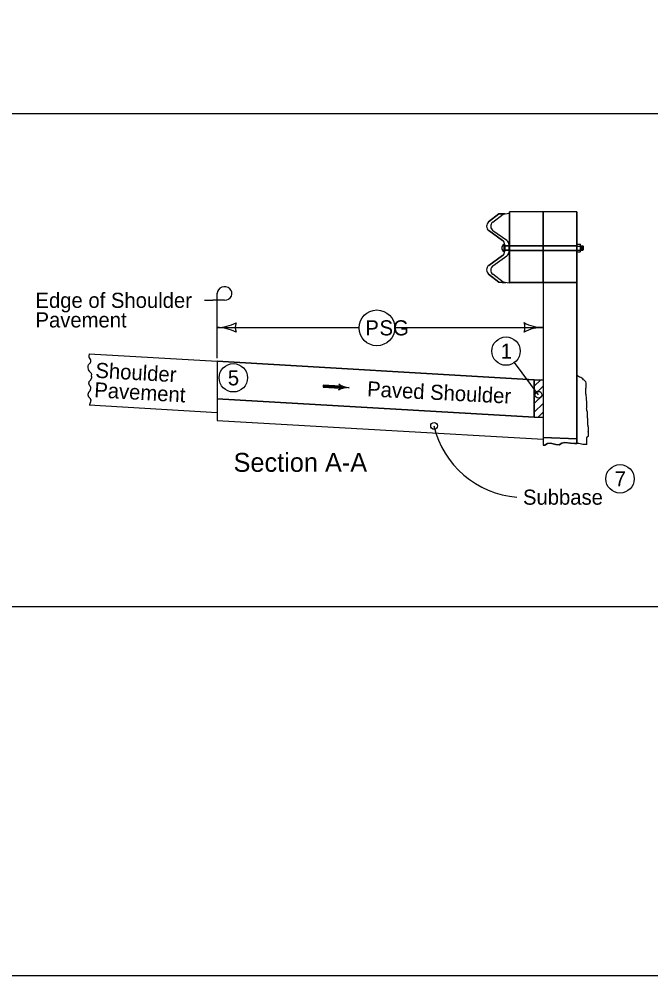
# Model space of a CAD drawing. Extents: x 8045 to 81668, y 6217 to 16762.
# Drawn here: x 10335 to 11002, y 7924 to 8935 of the extents above; entities that cross this region are included whole.
import ezdxf

# ---------------------------------------------------------------- set-up
doc = ezdxf.new("R2010")
doc.units = 0
for name, color, linetype in [('dsnStdDetailExtension', 7, 'Continuous'), ('dsnStdDimension', 7, 'Continuous'), ('dsnStdLabel', 7, 'Continuous'), ('dsnStdLineWork', 7, 'Continuous'), ('dsnStdPattern', 7, 'Continuous'), ('dsnStdSection', 7, 'Continuous'), ('Level 4', 7, 'Continuous'), ('Level 8', 7, 'Continuous'), ('TextBlockOut', 7, 'Continuous')]:
    doc.layers.add(name, color=color, linetype=linetype)

msp = doc.modelspace()

# ---------------------------------------------------------------- linework, layer by layer
at = {"layer": 'dsnStdDetailExtension'}
msp.add_circle((10773.3, 8505.4), 3.54, dxfattribs=at)
msp.add_circle((10773.3, 8505.4), 3.54, dxfattribs=at)
at = {"layer": 'dsnStdDimension'}
msp.add_line((10152.2, 8314.4), (13247.9, 8314.4), dxfattribs=at)
at = {"layer": 'dsnStdLabel'}
for p, q in [((10831, 8721.1), (10841.8, 8729.5)), ((10835.4, 8720.8), (10846.2, 8729.3)), ((10841.8, 8729.5), (10848.1, 8729.6)), ((10846.2, 8729.3), (10852.6, 8730.4)), ((10924.1, 8731.8), (10853, 8731.8)), ((10853, 8657.2), (10853, 8731.8)), ((10888.5, 8657.2), (10888.5, 8731.8)), ((10924.1, 8731.8), (10924.1, 8486.8)), ((10845.7, 8701.5), (10831.2, 8712)), ((10850.2, 8701.3), (10835.6, 8711.8)), ((10924.1, 8700.1), (10924.7, 8700.1)), ((10924.7, 8686.8), (10924.7, 8700.1)), ((10847.3, 8689.4), (10847.3, 8697.5)), ((10847.3, 8695.8), (10852.8, 8695.8)), ((10847.3, 8691.2), (10853, 8691.2)), ((10848.1, 8690.1), (10848.1, 8696.9)), ((10848.1, 8690.1), (10848.1, 8693.5)), ((10848.1, 8693.5), (10848.1, 8690.1)), ((10848.3, 8695.8), (10853, 8695.8)), ((10852.6, 8693.3), (10852.6, 8696.7)), ((10852.6, 8689.9), (10852.6, 8693.3)), ((10852.6, 8693.3), (10852.6, 8689.9)), ((10853, 8696.2), (10924.1, 8696.2)), ((10853, 8695.8), (10924.1, 8695.8)), ((10853, 8691.2), (10924.1, 8691.2)), ((10853, 8690.8), (10924.1, 8690.8)), ((10924.7, 8697.5), (10927.7, 8697.5)), ((10924.7, 8695.5), (10927.7, 8695.5)), ((10924.7, 8691.4), (10927.7, 8691.4)), ((10924.7, 8689.4), (10927.7, 8689.4)), ((10928.1, 8690.4), (10928.1, 8696.5)), ((10928.1, 8695.8), (10930.4, 8695.8)), ((10928.1, 8691.1), (10930.4, 8691.1)), ((10929, 8695.8), (10929, 8691.1)), ((10929.7, 8695.8), (10929.7, 8691.1)), ((10930.4, 8695.8), (10930.9, 8695.3)), ((10930.4, 8695.8), (10930.4, 8691.1)), ((10930.9, 8691.7), (10930.4, 8691.1)), ((10930.9, 8695.3), (10930.9, 8691.7)), ((10831.2, 8675.1), (10845.7, 8685.5)), ((10835.6, 8674.8), (10850.2, 8685.3)), ((10924.1, 8686.8), (10924.7, 8686.8)), ((10841.8, 8657.5), (10831, 8665.9)), ((10846.2, 8657.3), (10835.4, 8665.7)), ((10848.9, 8656.8), (10841.8, 8657.5)), ((10852.6, 8656.2), (10846.2, 8657.3)), ((10888.5, 8657.2), (10853, 8657.2)), ((10888.5, 8657.2), (10888.5, 8485)), ((10409, 8581.6), (10544.1, 8573.7)), ((10544.1, 8573.7), (10544.1, 8519.7)), ((10544.1, 8573.7), (10879.2, 8554.2)), ((10879.2, 8547.5), (10886, 8554.2)), ((10879.2, 8547.5), (10886, 8554.2)), ((10879.2, 8547.5), (10886, 8554.2)), ((10879.2, 8547.5), (10886, 8554.2)), ((10879.2, 8554.2), (10888.5, 8554.2)), ((10879.2, 8554.2), (10879.2, 8514.8)), ((10879.2, 8538.3), (10888.5, 8547.5)), ((10879.2, 8538.3), (10888.5, 8547.5)), ((10879.2, 8538.3), (10888.5, 8547.5)), ((10879.2, 8538.3), (10888.5, 8547.5)), ((10934.1, 8547.5), (10934.1, 8547.5)), ((10879.2, 8529.1), (10888.5, 8538.3)), ((10879.2, 8529.1), (10888.5, 8538.3)), ((10879.2, 8529.1), (10888.5, 8538.3)), ((10879.2, 8529.1), (10888.5, 8538.3)), ((10409, 8527.6), (10544.1, 8519.7)), ((10879.2, 8514.8), (10544.1, 8534.1)), ((10879.2, 8519.8), (10888.5, 8529.1)), ((10544.1, 8519.7), (10544.1, 8511.3)), ((10883.3, 8514.8), (10888.5, 8519.9)), ((10544.1, 8511.3), (10888.5, 8491.4)), ((10879.2, 8514.8), (10888.5, 8514.8))]:
    msp.add_line(p, q, dxfattribs=at)
for points in [[(10927.8, 8695.5), (10927.8, 8695.5), (10927.9, 8695.6), (10928, 8695.9), (10928, 8696.1), (10928, 8694.2), (10928, 8694.7), (10927.9, 8695.1), (10927.8, 8695.4), (10927.8, 8695.5), (10927.8, 8695.5), (10927.9, 8695.6), (10928, 8695.9), (10928, 8696), (10928, 8694.5), (10928, 8695), (10927.9, 8695.2), (10927.8, 8695.5), (10927.8, 8695.5), (10928, 8695.7), (10928, 8695.9), (10928, 8694.7), (10927.8, 8695.5), (10928, 8695.7), (10928, 8694.9), (10927.8, 8695.4), (10928, 8695.7), (10928, 8695), (10927.9, 8695.4), (10928, 8695.6), (10928, 8695.2), (10927.9, 8695.4), (10927.9, 8695.5), (10927.9, 8695.3), (10927.9, 8695.4), (10927.9, 8695.4)], [(10928, 8690.8), (10928, 8691), (10928, 8691.2), (10927.9, 8691.4), (10927.8, 8691.5), (10927.8, 8691.5), (10927.9, 8691.8), (10928, 8692.1), (10928.1, 8692.8), (10928, 8690.8), (10928, 8690.9), (10928, 8691.1), (10927.9, 8691.3), (10927.8, 8691.4), (10927.8, 8691.5), (10927.9, 8691.7), (10928, 8692.2), (10928, 8692.6), (10928, 8691), (10928, 8691.1), (10928, 8691.2), (10927.8, 8691.4), (10927.9, 8691.6), (10928, 8691.9), (10928, 8692.3), (10928, 8691.1), (10928, 8691.2), (10927.9, 8691.4), (10927.9, 8691.6), (10928, 8691.9), (10928, 8692.1), (10928, 8691.2), (10927.9, 8691.3), (10927.9, 8691.4), (10928, 8691.9), (10928, 8691.3), (10927.9, 8691.4), (10927.9, 8691.7), (10927.9, 8691.4), (10927.9, 8691.4), (10927.9, 8691.5), (10927.9, 8691.5)], [(10934.6, 8523.6), (10934.5, 8523.3), (10934.5, 8523.1), (10934.5, 8523), (10934.5, 8522.8), (10934.5, 8522.6), (10934.5, 8522.4), (10934.5, 8522.1), (10934.5, 8521.9), (10934.6, 8521.6), (10934.7, 8521.3), (10934.9, 8521.1), (10934.9, 8520.9), (10935, 8520.7), (10935, 8520.5), (10935, 8520.3), (10935.1, 8520.2), (10935.1, 8520), (10935.1, 8519.8), (10935.1, 8519.6), (10935.1, 8519.4), (10935.1, 8519.2), (10935.1, 8518.9), (10935.1, 8518.7), (10935.1, 8518.5), (10935.1, 8518.2), (10935.1, 8518), (10935.1, 8517.8), (10935.2, 8517.7), (10935.2, 8517.5), (10935.2, 8517.3), (10935.2, 8517.1), (10935.2, 8516.9), (10935.2, 8516.7), (10935.2, 8516.5), (10935.2, 8516.3), (10935.2, 8516.1), (10935.2, 8515.9), (10935.2, 8515.7), (10935.2, 8515.5), (10935.2, 8515.3), (10935.2, 8515.1), (10935.2, 8514.9), (10935.2, 8514.7), (10935.2, 8514.6), (10935.2, 8514.4), (10935.2, 8514.2), (10935.3, 8514.1), (10935.3, 8513.9), (10935.3, 8513.7), (10935.4, 8513.6), (10935.4, 8513.4), (10935.4, 8513.2), (10935.5, 8513.1), (10935.5, 8512.9), (10935.5, 8512.7), (10935.5, 8512.5), (10935.5, 8512.2), (10935.6, 8511.9), (10935.6, 8511.7), (10935.6, 8511.5), (10935.6, 8511.3), (10935.6, 8511.1), (10935.6, 8510.9), (10935.6, 8510.7), (10935.6, 8510.5), (10935.6, 8510.4), (10935.6, 8510.2), (10935.6, 8510), (10935.6, 8509.8), (10935.6, 8509.6), (10935.6, 8509.4), (10935.6, 8509.2), (10935.6, 8509), (10935.6, 8508.8), (10935.6, 8508.6), (10935.6, 8508.4), (10935.6, 8508.2), (10935.6, 8508), (10935.6, 8507.8), (10935.6, 8507.6), (10935.6, 8507.4), (10935.6, 8507.2), (10935.6, 8507), (10935.6, 8506.8), (10935.6, 8506.6), (10935.6, 8506.4), (10935.6, 8506.2), (10935.7, 8506.1), (10935.7, 8505.9), (10935.7, 8505.7), (10935.8, 8505.5), (10935.9, 8505.2), (10935.9, 8505), (10936, 8504.9), (10936, 8504.7), (10936.1, 8504.6), (10936.2, 8504.5), (10936.2, 8504.3), (10936.2, 8504.1), (10936.2, 8503.9), (10936.3, 8503.8), (10936.3, 8503.6), (10936.3, 8503.4), (10936.3, 8503.2), (10936.3, 8503), (10936.3, 8502.8), (10936.3, 8502.6), (10936.3, 8502.4), (10936.3, 8502.2), (10936.3, 8502), (10936.3, 8501.9), (10936.3, 8501.7), (10936.3, 8501.5), (10936.3, 8501.3), (10936.3, 8501.1), (10936.3, 8500.9), (10936.3, 8500.7), (10936.3, 8500.5), (10936.3, 8500.3), (10936.3, 8500.1), (10936.3, 8499.9), (10936.3, 8499.7), (10936.3, 8499.5), (10936.3, 8499.3), (10936.3, 8499.1), (10936.3, 8498.9), (10936.3, 8498.9), (10936.3, 8499.2), (10936.3, 8499.4), (10936.3, 8499.6), (10936.3, 8499.4), (10936.3, 8499.2), (10936.3, 8499), (10936.3, 8498.8), (10936.3, 8498.6), (10936.3, 8498.4), (10936.3, 8498.2), (10936.3, 8498), (10936.3, 8497.8), (10936.3, 8497.6), (10936.3, 8497.5), (10936.3, 8497.3), (10936.3, 8497.1), (10936.3, 8496.9), (10936.3, 8496.7), (10936.2, 8496.6), (10936.2, 8496.4), (10936.2, 8496.2), (10936.2, 8496), (10936.2, 8495.8), (10936.2, 8495.6), (10936.2, 8495.4), (10936.2, 8495.2), (10936.2, 8495), (10936.2, 8494.8), (10936.2, 8494.6), (10936.1, 8494.5), (10936, 8494.3), (10935.9, 8494.2), (10935.8, 8494.1), (10935.7, 8494), (10935.5, 8493.9), (10935.3, 8493.9), (10935.2, 8493.8), (10935.1, 8493.7), (10935, 8493.6), (10934.8, 8493.5), (10934.7, 8493.4), (10934.7, 8493.3), (10934.6, 8493.2), (10934.6, 8493), (10934.6, 8492.8), (10934.6, 8492.6), (10934.6, 8485.8)], [(10934.7, 8485.8), (10930.6, 8485.6), (10926.5, 8486.8), (10921.9, 8486.8), (10917.7, 8487.2), (10911.4, 8488), (10908.3, 8487.3), (10905.7, 8485.5), (10902, 8485.7), (10896.4, 8487.3), (10893.1, 8486.8), (10890.3, 8485.2), (10888.5, 8485)]]:
    msp.add_lwpolyline(points, dxfattribs=at)
for centre, radius, start, end in [((10834.5, 8716.6), 5.68, 127.75, 234.6909), ((10838.9, 8716.4), 5.68, 127.75, 234.6909), ((10842.4, 8696.9), 5.68, 360, 54.691), ((10846.9, 8696.7), 5.68, 360, 54.691), ((10849.4, 8693.5), 4.54, 117.2029, 242.8461), ((10842.4, 8690.1), 5.68, 305.309, 0), ((10846.9, 8689.9), 5.68, 305.309, 0), ((10834.5, 8670.4), 5.68, 125.3091, 232.25), ((10838.9, 8670.2), 5.68, 125.3091, 232.25)]:
    msp.add_arc(centre, radius, start, end, dxfattribs=at)
for centre in [(10927.7, 8696.5), (10927.7, 8690.4)]:
    msp.add_ellipse(centre, major_axis=(0, -1.01), ratio=0.362258, start_param=6.283156, end_param=9.424748, dxfattribs=at)
for points in [[(10409, 8581.6), (10408.5, 8578), (10409.5, 8576.5), (10410.4, 8574.2), (10409.8, 8572.1), (10407.9, 8569.7), (10407.3, 8567.8), (10407.9, 8565.5), (10408.7, 8563.2), (10409.8, 8562.4), (10411.2, 8559.9), (10411.1, 8559.1)], [(10409.2, 8542), (10409.4, 8542.2), (10409.6, 8542.5), (10409.9, 8543), (10410.2, 8543.6), (10410.3, 8543.9), (10410.4, 8544.2), (10410.6, 8544.9), (10410.6, 8545.5), (10410.6, 8546.1), (10410.5, 8546.3), (10410.5, 8546.5), (10410.4, 8546.6), (10410.2, 8547), (10409.9, 8547.4), (10409.6, 8547.7), (10409.4, 8548.1), (10409.3, 8548.4), (10409.1, 8548.7), (10408.9, 8549.3), (10408.7, 8549.8), (10408.6, 8550.1), (10408.5, 8550.4), (10408.5, 8550.5), (10408.5, 8550.7), (10408.7, 8551.4), (10408.9, 8552), (10409.1, 8552.5), (10409.6, 8553.1), (10410.1, 8553.7), (10410.6, 8554.2), (10410.8, 8554.5), (10411, 8554.8), (10411.2, 8555.3), (10411.4, 8555.8), (10411.5, 8556.3), (10411.5, 8556.5), (10411.6, 8556.6), (10411.6, 8556.7), (10411.5, 8557.3), (10411.4, 8557.8), (10411.3, 8557.9), (10411.3, 8558), (10411.2, 8558.2), (10411.2, 8558.3), (10411.1, 8559.1)], [(10934.6, 8523.6), (10934.9, 8526.5), (10934.7, 8531.4), (10934.2, 8537.1), (10933.6, 8541.6), (10933.8, 8544.9), (10934.2, 8549.1), (10933.6, 8552.2), (10931.4, 8554.2), (10929.4, 8555.9), (10927.2, 8557), (10924.9, 8558.4), (10924.1, 8559)], [(10409.2, 8542), (10409, 8541.7), (10408.7, 8541.5), (10408.5, 8541.2), (10408.3, 8541), (10408.2, 8540.7), (10408, 8540.4), (10407.8, 8539.8), (10407.7, 8539.6), (10407.6, 8539.3), (10407.5, 8539), (10407.5, 8538.8), (10407.4, 8538.7), (10407.4, 8538.2), (10407.6, 8537.7), (10407.8, 8537.1), (10408, 8536.6), (10408.5, 8536), (10409, 8535.4), (10409.5, 8534.9), (10409.8, 8534.6), (10410, 8534.2), (10410.4, 8533.3), (10410.5, 8532.8), (10410.5, 8532.3), (10410.4, 8532.1), (10410.4, 8531.8), (10410.3, 8531.5), (10410.3, 8531.2), (10410, 8530.1), (10409.8, 8529.4), (10409.6, 8528.8), (10409.4, 8528.3), (10409.2, 8528), (10409.1, 8527.7), (10409, 8527.6)]]:
    msp.add_spline(points, degree=3, dxfattribs=at)
at = {"layer": 'dsnStdLineWork'}
for p, q in [((10530.7, 8638.2), (10539.4, 8638.2)), ((10551.9, 8638.2), (10539.4, 8638.2)), ((10544.1, 8625.4), (10544.1, 8646.2)), ((10544.1, 8576.9), (10544.1, 8625.4)), ((10544.1, 8609.5), (10693.9, 8609.5)), ((10731.8, 8609.6), (10888.5, 8609.6)), ((10674.3, 8546.4), (10656.1, 8547.4)), ((10674.3, 8547.4), (10674.3, 8547.4)), ((10674.2, 8545.4), (10674.2, 8545.4))]:
    msp.add_line(p, q, dxfattribs=at)
for points in [[(10674.4, 8547.3), (10656.2, 8548.4), (10656.1, 8546.5), (10674.2, 8545.4), (10674.3, 8547), (10656.4, 8548.1), (10656.3, 8546.6), (10673.8, 8545.7), (10674, 8546.8), (10656.6, 8547.9), (10656.6, 8546.9), (10673.6, 8545.9), (10673.7, 8546.6), (10656.8, 8547.7), (10656.8, 8547.1), (10673.4, 8546.2)], [(10673.9, 8548.6), (10674.6, 8547.4), (10674.6, 8545.7), (10673.9, 8544.4), (10676.6, 8545.2), (10679.8, 8545.9), (10680.7, 8546), (10678.5, 8546.5), (10675.2, 8547.8), (10674.3, 8548.3), (10674.4, 8544.8), (10679.4, 8546), (10674.7, 8547.6), (10674.7, 8545.2), (10678.1, 8546.1), (10675.1, 8547), (10674.9, 8545.6), (10677.1, 8546.1), (10675.5, 8546.6), (10675.3, 8545.9), (10676.1, 8546.1)]]:
    msp.add_lwpolyline(points, dxfattribs=at)
msp.add_circle((10712.9, 8609.1), 18.9, dxfattribs=at)
for centre, radius, start, end in [((10544.1, 8652), 42.5, 270, 298.0725), ((10544.1, 8567), 42.5, 61.9275, 90), ((10579.7, 8609.5), 16.4, 162.2666, 197.7334), ((10852.9, 8609.6), 16.4, 342.2666, 17.7333), ((10888.5, 8652.1), 42.5, 241.9275, 270), ((10888.5, 8567.1), 42.5, 90, 118.0725), ((10868.5, 8527.6), 97.8, 193.077, 265.558)]:
    msp.add_arc(centre, radius, start, end, dxfattribs=at)
for centre, major_axis, start_param, end_param in [((10551.9, 8645.4), (-7.81, 0), 1.570796, 6.283185), ((10670.6, 8546.6), (3.88, 0), 5.202895, 7.237436), ((10685.6, 8566), (-22.2, 0), 0.954258, 1.478381), ((10682.8, 8525.6), (22.2, 0), 1.537172, 2.061295)]:
    msp.add_ellipse(centre, major_axis=major_axis, ratio=0.913811, start_param=start_param, end_param=end_param, dxfattribs=at)
at = {"layer": 'dsnStdPattern'}
for p, q in [((10831.2, 8712), (10845.7, 8701.5)), ((10845.7, 8685.5), (10831.2, 8675.1)), ((10879.3, 8554.2), (10544.1, 8573.7)), ((10544.1, 8573.7), (10544.1, 8534.1)), ((10879.3, 8514.8), (10879.3, 8554.2)), ((10544.1, 8534.1), (10879.3, 8514.8))]:
    msp.add_line(p, q, dxfattribs=at)
for points in [[(10835.5, 8720.9), (10835.4, 8720.8), (10846.2, 8729.3), (10848.1, 8729.6), (10841.8, 8729.5), (10831, 8721.1)], [(10888.5, 8696.2), (10888.5, 8731.8), (10853, 8731.8), (10853, 8696.2), (10853, 8696.2), (10888.5, 8696.2)], [(10924.1, 8696.2), (10924.1, 8700.2), (10924.1, 8731.8), (10888.5, 8731.8), (10888.5, 8696.2), (10924.1, 8696.2)], [(10850.2, 8701.3), (10850.2, 8701.3), (10835.6, 8711.8), (10835.7, 8711.7)], [(10848.1, 8696.9), (10848.1, 8695.8), (10852.6, 8695.8), (10852.6, 8696.7), (10852.6, 8696.7)], [(10852.6, 8689.9), (10852.6, 8689.9), (10852.6, 8691.2), (10848.1, 8691.2), (10848.1, 8690.1), (10848.1, 8691.2), (10848.1, 8691.2), (10848.1, 8690.1)], [(10853, 8695.8), (10853, 8691.2), (10853, 8691.2), (10888.5, 8691.2), (10888.5, 8695.8), (10853, 8695.8), (10853, 8695.8)], [(10853, 8690.8), (10853, 8657.2), (10888.5, 8657.2), (10888.5, 8690.8), (10853, 8690.8)], [(10924.1, 8691.2), (10924.1, 8695.8), (10888.5, 8695.8), (10888.5, 8691.2), (10924.1, 8691.2)], [(10924.1, 8657.2), (10924.1, 8686.8), (10924.1, 8690.8), (10888.5, 8690.8), (10888.5, 8657.2), (10924.1, 8657.2)], [(10835.7, 8674.8), (10835.6, 8674.8), (10850.2, 8685.3), (10850.2, 8685.2)], [(10831, 8665.9), (10841.8, 8657.5), (10848.9, 8656.8), (10846.2, 8657.3), (10835.4, 8665.7), (10835.5, 8665.7)], [(10924.1, 8491.9), (10924.1, 8657.2), (10888.5, 8657.2), (10888.5, 8554.2), (10888.5, 8547.5), (10888.5, 8547.5), (10888.5, 8547.5), (10888.5, 8538.3), (10888.5, 8538.3), (10888.5, 8538.3), (10888.5, 8529.2), (10888.5, 8529.2), (10888.5, 8529.2), (10888.5, 8522.2), (10888.5, 8493), (10924.1, 8491.9)], [(10924.1, 8491.9), (10888.5, 8493), (10888.5, 8485), (10890.3, 8485.2), (10893.1, 8486.8), (10896.4, 8487.3), (10902, 8485.7), (10905.7, 8485.5), (10908.3, 8487.3), (10911.4, 8488), (10917.7, 8487.2), (10921.9, 8486.8), (10924.1, 8486.8), (10924.1, 8491.9)]]:
    msp.add_lwpolyline(points, dxfattribs=at)
msp.add_lwpolyline([(10852.6, 8695.8), (10848.1, 8695.8), (10848.1, 8692.4), (10848.1, 8693.5), (10848.1, 8691.2), (10852.6, 8691.2)], close=True, dxfattribs=at)
for centre, start, end in [((10834.5, 8716.6), 127.75, 234.6909), ((10838.9, 8716.4), 127.75, 234.6909), ((10842.4, 8696.9), 0, 54.691), ((10846.9, 8696.7), 0, 54.691), ((10842.4, 8690.1), 305.309, 0), ((10846.9, 8689.9), 305.309, 0), ((10834.5, 8670.4), 125.3091, 232.25), ((10838.9, 8670.2), 125.3091, 232.25)]:
    msp.add_arc(centre, 5.68, start, end, dxfattribs=at)
at = {"layer": 'dsnStdSection'}
msp.add_lwpolyline([(10132.5, 9944), (13267.5, 9944), (13267.5, 7924), (10132.5, 7924)], close=True, dxfattribs=at)
at = {"layer": 'Level 4'}
for p, q in [((12307.8, 8835.4), (10152.2, 8835.4)), ((10883.6, 8538.4), (10858.2, 8572.3))]:
    msp.add_line(p, q, dxfattribs=at)
at = {"layer": 'Level 8'}
for centre, radius in [((10849.4, 8584.5), 15), ((10561.2, 8556.3), 15), ((10883.6, 8538.4), 3.58), ((10969.9, 8449.5), 15)]:
    msp.add_circle(centre, radius, dxfattribs=at)
at = {"layer": 'TextBlockOut'}
msp.add_circle((10561.2, 8556.3), 15, dxfattribs=at)

# ---------------------------------------------------------------- texts
at = {"layer": 'dsnStdLineWork'}
for s, height, p in [('Edge of Shoulder ', 16, (10352.1, 8630.2)), ('Pavement', 16, (10352.1, 8609.5)), ('P', 16, (10700.7, 8601.1)), ('SG', 16, (10715.7, 8601.1)), ('Section A-A', 20, (10561.4, 8456.9)), ('Subbase', 16, (10867.3, 8422.1))]:
    msp.add_text(s, height=height, dxfattribs=at).set_placement(p)
for s, rotation, p in [('Shoulder', 356.7346, (10415.1, 8556.4)), ('Pavement', 356.7346, (10413.9, 8535.7)), ('Paved Shoulder ', 357.0678, (10702.3, 8536.7))]:
    msp.add_text(s, height=16, rotation=rotation, dxfattribs=at).set_placement(p)
at = {"layer": 'Level 8'}
for s, p in [('1', (10843.8, 8576.5)), ('5', (10555.4, 8548.3)), ('7', (10964.2, 8441.5))]:
    msp.add_text(s, height=16, dxfattribs=at).set_placement(p)

doc.saveas('drawing.dxf')
